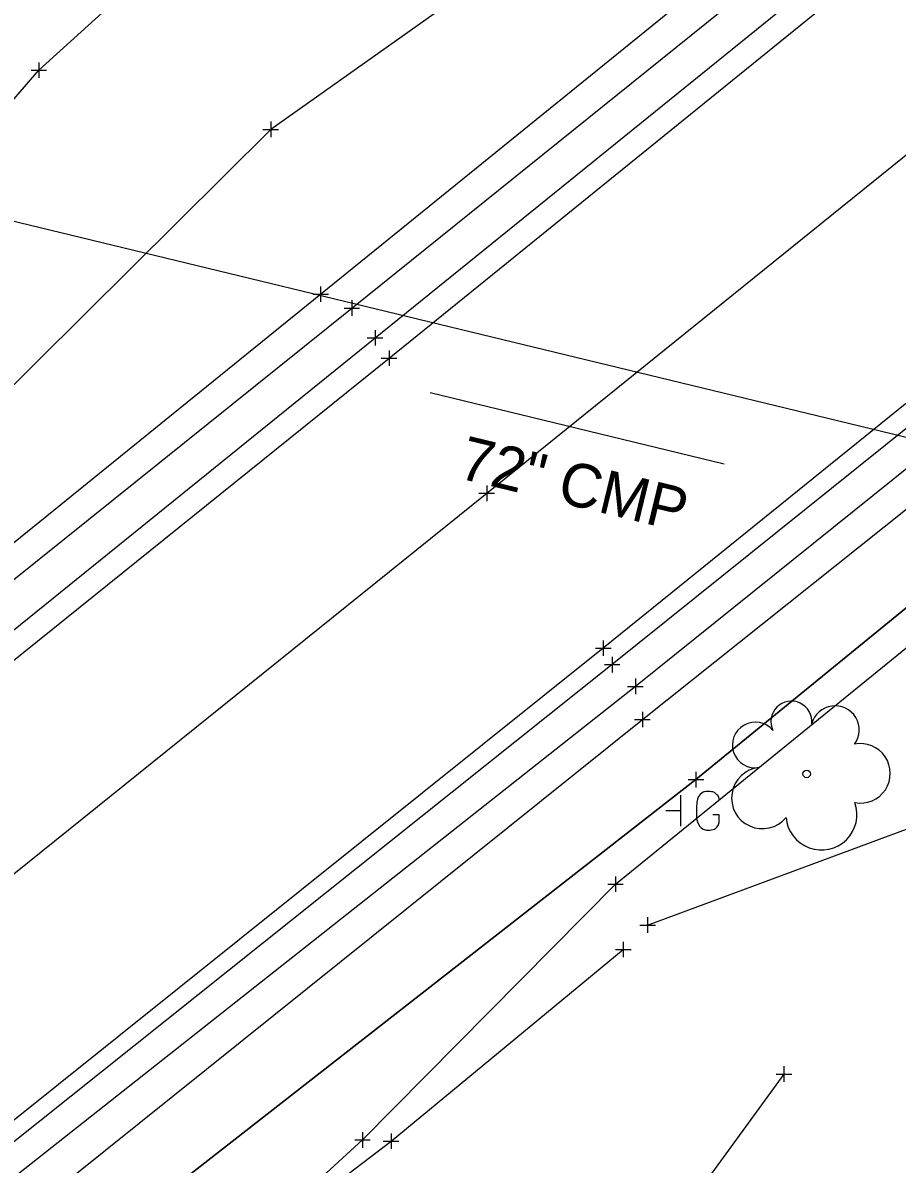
# Model space of a CAD drawing. Extents: x 2184635 to 2185378, y 369880 to 370486.
# Drawn here: x 2185109.3 to 2185165.6, y 370246.3 to 370319.8 of the extents above; entities that cross this region are included whole.
import ezdxf

# ---------------------------------------------------------------- set-up
doc = ezdxf.new("R2010")
doc.units = 0
for name, color, linetype in [('DR_X_Ditch', 7, 'Continuous'), ('DR_X_Storm_Sewer', 7, 'Continuous'), ('DR_X_Text', 7, 'Continuous'), ('GE_X_Alignment', 7, 'Continuous'), ('GE_X_Alignment_100_Bearings', 7, 'Continuous'), ('GE_X_Alignment_100_Distances', 7, 'Continuous'), ('PM_X_CL_Pass_Proh_Lt', 7, 'Continuous'), ('PM_X_CL_Pass_Proh_Rt', 7, 'Continuous'), ('PM_X_Edge_Line', 7, 'Continuous'), ('PV_X_COP', 7, 'Continuous'), ('PV_X_EOP', 7, 'Continuous'), ('PV_X_Shoulder', 7, 'Continuous'), ('RD_X_Fence', 7, 'Continuous'), ('RD_X_GR_Lt', 7, 'Continuous'), ('RD_X_GR_Rt', 7, 'Continuous'), ('RW_X_CL', 7, 'Continuous'), ('SV_X_Break_Lines', 7, 'Continuous'), ('UT_X_Gas', 7, 'Continuous')]:
    doc.layers.add(name, color=color, linetype=linetype)

msp = doc.modelspace()

# ---------------------------------------------------------------- linework, layer by layer
at = {"layer": 'DR_X_Ditch'}
msp.add_lwpolyline([(2185149.532, 370261.732), (2185173.227, 370270.512), (2185185.361, 370271.623), (2185194.823, 370274.626), (2185197.504, 370277.588), (2185197.594, 370279.178), (2185198.93, 370282.292)], dxfattribs=at)
at = {"layer": 'DR_X_Storm_Sewer'}
msp.add_line((2185197.669, 370285.467), (2185098.296, 370309.544), dxfattribs=at)
at = {"layer": 'DR_X_Text'}
msp.add_line((2185135.542, 370295.992), (2185154.464, 370291.408), dxfattribs=at)
at = {"layer": 'GE_X_Alignment'}
msp.add_circle((2185159.76, 370271.452), 0.24, dxfattribs=at)
for centre, radius, start, end in [((2185158.777, 370274.82), 1.317, 354.0047, 205.97412), ((2185161.587, 370274.281), 1.553, 323.82996, 165.0376), ((2185156.451, 370273.316), 1.471, 39.06254, 279.54124), ((2185163.221, 370271.488), 1.915, 259.14531, 101.45961), ((2185156.907, 370269.904), 1.974, 96.17219, 320.57371), ((2185160.707, 370268.847), 2.284, 184.94757, 19.45715)]:
    msp.add_arc(centre, radius, start, end, dxfattribs=at)
at = {"layer": 'GE_X_Alignment_100_Bearings'}
for p, q in [((2185151.664, 370268.082), (2185151.664, 370270.082)), ((2185151.664, 370269.082), (2185150.712, 370269.082))]:
    msp.add_line(p, q, dxfattribs=at)
msp.add_lwpolyline([(2185154.141, 370269.838), (2185154.121, 370269.937), (2185154.062, 370270.035), (2185153.963, 370270.134), (2185153.826, 370270.252), (2185153.727, 370270.291), (2185153.648, 370270.311), (2185153.53, 370270.331), (2185153.294, 370270.331), (2185153.196, 370270.311), (2185153.137, 370270.291), (2185153.058, 370270.252), (2185152.9, 370270.134), (2185152.802, 370269.996), (2185152.743, 370269.838), (2185152.704, 370269.622), (2185152.664, 370269.307), (2185152.664, 370268.893), (2185152.684, 370268.559), (2185152.763, 370268.303), (2185152.881, 370268.067), (2185152.979, 370267.988), (2185153.097, 370267.909), (2185153.314, 370267.831), (2185153.53, 370267.831), (2185153.747, 370267.87), (2185153.826, 370267.909), (2185153.904, 370267.949), (2185153.983, 370268.027), (2185154.062, 370268.145), (2185154.141, 370268.323), (2185154.141, 370268.815), (2185153.727, 370268.815)], dxfattribs=at)
at = {"layer": 'GE_X_Alignment_100_Distances'}
for points in [[(2185064.938, 370249.915), (2185090.369, 370269.214), (2185130.506, 370301.429), (2185168.462, 370331.991), (2185206.748, 370363.667), (2185245.64, 370395.454)], [(2185264.317, 370371.308), (2185225.669, 370339.838), (2185186.917, 370307.744), (2185148.745, 370277.089), (2185109.073, 370245.724), (2185070.468, 370214.753), (2185031.044, 370183.419), (2184991.951, 370153.137), (2184952.243, 370122.384), (2184912.885, 370091.687), (2184876.597, 370062.99), (2184874.528, 370062.204), (2184872.479, 370060.466), (2184871.454, 370058.823), (2184869.46, 370057.791), (2184834.83, 370028.947), (2184796.151, 369998.173), (2184773.728, 369979.618), (2184757.686, 369965.832), (2184717.275, 369935.855), (2184678.357, 369904.181)]]:
    msp.add_lwpolyline(points, dxfattribs=at)
at = {"layer": 'PM_X_CL_Pass_Proh_Lt'}
msp.add_lwpolyline([(2185262.142, 370374.202), (2185223.699, 370342.03), (2185185.178, 370310.659), (2185146.677, 370279.544), (2185107.738, 370248.35), (2185068.5, 370216.963), (2185029.051, 370186.04), (2184989.472, 370156.275), (2184949.89, 370125.369), (2184910.765, 370094.563), (2184870.979, 370063.529), (2184832.077, 370032.401), (2184793.204, 370001.486), (2184754.34, 369970.024), (2184715.121, 369938.505), (2184676.144, 369907.221)], dxfattribs=at)
at = {"layer": 'PM_X_CL_Pass_Proh_Rt'}
msp.add_lwpolyline([(2184772.075, 369998.33), (2184786.357, 370009.443), (2184824.962, 370040.257), (2184864.241, 370071.885), (2184905.968, 370104.805), (2184943.399, 370133.995), (2184983.483, 370165.213), (2185020.257, 370194.467), (2185061.224, 370226.635), (2185099.743, 370257.779), (2185139.182, 370289.511), (2185177.352, 370320.307), (2185216.054, 370351.804), (2185254.728, 370383.452)], dxfattribs=at)
at = {"layer": 'PM_X_Edge_Line'}
msp.add_lwpolyline([(2184661.525, 369922.948), (2184702.122, 369955.424), (2184740.459, 369986.306), (2184779.792, 370018.036), (2184818.421, 370048.832), (2184857.458, 370080.192), (2184899.139, 370112.801), (2184937.357, 370142.735), (2184976.78, 370173.64), (2185013.226, 370203.926), (2185054.743, 370235.213), (2185093.131, 370266.204), (2185132.902, 370298.208), (2185170.876, 370328.987), (2185209.713, 370360.437), (2185248.243, 370392.049)], dxfattribs=at)
at = {"layer": 'PV_X_COP'}
msp.add_lwpolyline([(2184667.936, 369914.544), (2184708.437, 369946.755), (2184746.444, 369977.522), (2184786.357, 370009.443), (2184824.962, 370040.257), (2184864.241, 370071.885), (2184905.968, 370104.805), (2184943.399, 370133.995), (2184983.483, 370165.213), (2185020.257, 370194.467), (2185061.224, 370226.635), (2185099.743, 370257.779), (2185139.182, 370289.511), (2185177.352, 370320.307), (2185216.054, 370351.804), (2185254.679, 370383.196)], dxfattribs=at)
at = {"layer": 'PV_X_EOP'}
for points in [[(2184661.562, 369922.858), (2184702.122, 369955.424), (2184740.459, 369986.306), (2184779.792, 370018.036), (2184818.421, 370048.832), (2184857.458, 370080.192), (2184899.139, 370112.801), (2184937.357, 370142.735), (2184976.78, 370173.64), (2185013.226, 370203.926), (2185054.743, 370235.213), (2185093.131, 370266.204), (2185132.902, 370298.208), (2185170.876, 370328.987), (2185209.713, 370360.437), (2185248.181, 370392.045)], [(2185262.152, 370374.256), (2185223.699, 370342.03), (2185185.178, 370310.659), (2185146.677, 370279.544), (2185107.738, 370248.35), (2185068.5, 370216.963), (2185029.051, 370186.04), (2184989.472, 370156.275), (2184949.89, 370125.369), (2184910.765, 370094.563), (2184870.979, 370063.529), (2184832.077, 370032.401), (2184793.204, 370001.486), (2184754.34, 369970.024), (2184715.121, 369938.505), (2184676.223, 369907.131)]]:
    msp.add_lwpolyline(points, dxfattribs=at)
at = {"layer": 'PV_X_Shoulder'}
for points in [[(2184660.616, 369924.653), (2184701.177, 369956.993), (2184739.308, 369987.689), (2184778.66, 370019.08), (2184817.145, 370050.202), (2184856.424, 370081.402), (2184897.962, 370114.276), (2184936.317, 370143.726), (2184975.811, 370174.815), (2184986.608, 370184.308), (2184994.082, 370192.548), (2185011.043, 370206.648), (2185033.171, 370224.287), (2185051.814, 370238.9), (2185062.885, 370246.964), (2185064.956, 370248.001), (2185067.328, 370248.113), (2185092.06, 370267.243), (2185132.002, 370299.513), (2185169.971, 370330.255), (2185208.837, 370361.607), (2185247.242, 370392.983)], [(2185263.127, 370373.08), (2185224.626, 370341.08), (2185185.979, 370309.587), (2185147.251, 370278.484), (2185108.316, 370247.412), (2185069.303, 370216.141), (2185029.865, 370185.151), (2184990.36, 370154.899), (2184951.083, 370123.826), (2184911.784, 370093.315), (2184872.077, 370062.156), (2184833.336, 370030.958), (2184794.18, 369999.967), (2184755.603, 369968.652), (2184716.02, 369937.324), (2184677.487, 369905.633)]]:
    msp.add_lwpolyline(points, dxfattribs=at)
at = {"layer": 'RD_X_Fence'}
msp.add_lwpolyline([(2184974.137, 370097.077), (2184970.447, 370119.306), (2184979.406, 370128.641), (2184992.607, 370140.381), (2185007.827, 370153.847), (2185011.099, 370157.209), (2185036.107, 370177.129), (2185063.41, 370198.922), (2185078.716, 370210.935), (2185113.226, 370240.316), (2185152.641, 370271.084), (2185187.441, 370299.506), (2185189.075, 370300.14), (2185213.006, 370319.114), (2185230.361, 370333.854), (2185268.576, 370364.897)], dxfattribs=at)
at = {"layer": 'RD_X_GR_Lt'}
msp.add_lwpolyline([(2185046.02, 370255.484), (2185051.058, 370252.105), (2185059.685, 370250.72), (2185069.217, 370254.599), (2185088.99, 370270.332), (2185128.498, 370302.326), (2185166.722, 370333.304), (2185205.522, 370364.756), (2185244.075, 370396.55), (2185351.751, 370485.271)], dxfattribs=at)
at = {"layer": 'RD_X_GR_Rt'}
msp.add_lwpolyline([(2184986.918, 370145.362), (2184992.997, 370150.672), (2185032.04, 370181.661), (2185071.402, 370212.899), (2185110.342, 370243.768), (2185149.195, 370274.959), (2185188, 370305.912), (2185226.97, 370337.52), (2185265.615, 370369.567), (2185308.993, 370405.417), (2185377.709, 370462.246)], dxfattribs=at)
at = {"layer": 'RW_X_CL'}
for p, q in [((2185109.877, 370316.731), (2185110.877, 370316.731)), ((2185110.377, 370317.231), (2185110.377, 370316.231)), ((2185110.377, 370316.731), (2185110.377, 370316.731)), ((2185124.789, 370312.922), (2185125.789, 370312.922)), ((2185125.289, 370313.422), (2185125.289, 370312.422)), ((2185125.289, 370312.922), (2185125.289, 370312.922)), ((2185128.498, 370302.826), (2185128.498, 370301.826)), ((2185127.998, 370302.326), (2185128.998, 370302.326)), ((2185128.498, 370302.326), (2185128.498, 370302.326)), ((2185130.506, 370301.929), (2185130.506, 370300.929)), ((2185130.006, 370301.429), (2185131.006, 370301.429)), ((2185130.506, 370301.429), (2185130.506, 370301.429)), ((2185132.002, 370300.013), (2185132.002, 370299.013)), ((2185131.502, 370299.513), (2185132.502, 370299.513)), ((2185132.002, 370299.513), (2185132.002, 370299.513)), ((2185132.902, 370298.708), (2185132.902, 370297.708)), ((2185132.902, 370298.708), (2185132.902, 370297.708)), ((2185132.402, 370298.208), (2185133.402, 370298.208)), ((2185132.402, 370298.208), (2185133.402, 370298.208)), ((2185132.902, 370298.208), (2185132.902, 370298.208)), ((2185132.902, 370298.208), (2185132.902, 370298.208)), ((2185138.682, 370289.511), (2185139.682, 370289.511)), ((2185138.682, 370289.511), (2185139.682, 370289.511)), ((2185139.182, 370290.011), (2185139.182, 370289.011)), ((2185139.182, 370290.011), (2185139.182, 370289.011)), ((2185139.182, 370289.511), (2185139.182, 370289.511)), ((2185139.182, 370289.511), (2185139.182, 370289.511)), ((2185146.677, 370280.044), (2185146.677, 370279.044)), ((2185146.677, 370280.044), (2185146.677, 370279.044)), ((2185146.177, 370279.544), (2185147.177, 370279.544)), ((2185146.177, 370279.544), (2185147.177, 370279.544)), ((2185146.677, 370279.544), (2185146.677, 370279.544)), ((2185146.677, 370279.544), (2185146.677, 370279.544)), ((2185146.751, 370278.484), (2185147.751, 370278.484)), ((2185147.251, 370278.984), (2185147.251, 370277.984)), ((2185147.251, 370278.484), (2185147.251, 370278.484)), ((2185148.245, 370277.089), (2185149.245, 370277.089)), ((2185148.745, 370277.589), (2185148.745, 370276.589)), ((2185148.745, 370277.089), (2185148.745, 370277.089)), ((2185148.695, 370274.959), (2185149.695, 370274.959)), ((2185149.195, 370275.459), (2185149.195, 370274.459)), ((2185149.195, 370274.959), (2185149.195, 370274.959)), ((2185152.141, 370271.084), (2185153.141, 370271.084)), ((2185152.141, 370271.084), (2185153.141, 370271.084)), ((2185152.641, 370271.584), (2185152.641, 370270.584)), ((2185152.641, 370271.584), (2185152.641, 370270.584)), ((2185152.641, 370271.084), (2185152.641, 370271.084)), ((2185152.641, 370271.084), (2185152.641, 370271.084)), ((2185147.466, 370264.862), (2185147.466, 370263.862)), ((2185146.966, 370264.362), (2185147.966, 370264.362)), ((2185147.466, 370264.362), (2185147.466, 370264.362)), ((2185149.032, 370261.732), (2185150.032, 370261.732)), ((2185149.532, 370262.232), (2185149.532, 370261.232)), ((2185149.532, 370261.732), (2185149.532, 370261.732)), ((2185147.463, 370260.154), (2185148.463, 370260.154)), ((2185147.963, 370260.654), (2185147.963, 370259.654)), ((2185147.963, 370260.154), (2185147.963, 370260.154)), ((2185157.8, 370252.143), (2185158.8, 370252.143)), ((2185158.3, 370252.643), (2185158.3, 370251.643)), ((2185158.3, 370252.143), (2185158.3, 370252.143)), ((2185131.189, 370248.401), (2185131.189, 370247.401)), ((2185133.03, 370248.325), (2185133.03, 370247.325)), ((2185130.689, 370247.901), (2185131.689, 370247.901)), ((2185131.189, 370247.901), (2185131.189, 370247.901)), ((2185132.53, 370247.825), (2185133.53, 370247.825)), ((2185133.03, 370247.825), (2185133.03, 370247.825))]:
    msp.add_line(p, q, dxfattribs=at)
at = {"layer": 'SV_X_Break_Lines'}
for points in [[(2185238.668, 370405.318), (2185202.581, 370371.499), (2185173.504, 370347.593), (2185162.544, 370339.328), (2185125.289, 370312.922), (2185086.214, 370274.11), (2185072.344, 370266.561), (2185063.517, 370264.024), (2185054.122, 370264.296), (2185046.494, 370262.377), (2185041.8, 370263.72), (2185037.874, 370271.942)], [(2185266.896, 370366.662), (2185229.269, 370335.467), (2185210.515, 370320.131), (2185189.044, 370300.271), (2185187.441, 370299.506), (2185152.641, 370271.084), (2185113.226, 370240.316), (2185078.716, 370210.935), (2185063.41, 370198.922), (2185036.107, 370177.129), (2185008.734, 370156.161), (2184994.285, 370149.68)], [(2185106.25, 370311.984), (2185110.377, 370316.731), (2185120.337, 370325.775), (2185107.52, 370320.878), (2185103.16, 370318.931), (2185102.793, 370313.909)], [(2185011.314, 370152.037), (2185029.522, 370165.964), (2185043.39, 370177.165), (2185060.22, 370191.124), (2185082.453, 370208.384), (2185104.298, 370224.36), (2185119.101, 370237.21), (2185133.03, 370247.825), (2185147.963, 370260.154)], [(2185158.3, 370252.143), (2185152.782, 370244.562), (2185135.708, 370225.876), (2185117.777, 370204.571), (2185084.693, 370178.208), (2185056.498, 370157.156)]]:
    msp.add_lwpolyline(points, dxfattribs=at)
at = {"layer": 'UT_X_Gas'}
msp.add_lwpolyline([(2184953.242, 370098.442), (2184967.159, 370111.339), (2184998.214, 370137.606), (2185039.424, 370172.123), (2185069.412, 370195.978), (2185086.695, 370210.093), (2185109.697, 370228.178), (2185131.189, 370247.901), (2185147.466, 370264.362), (2185212.955, 370317.623), (2185242.558, 370341.915), (2185269.196, 370362.683)], dxfattribs=at)

# ---------------------------------------------------------------- texts
at = {"layer": 'DR_X_Text'}
msp.add_text('72" CMP', height=2.8, rotation=346.38022, dxfattribs=at).set_placement((2185137.263, 370290.507))

doc.saveas('drawing.dxf')
